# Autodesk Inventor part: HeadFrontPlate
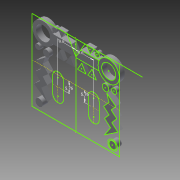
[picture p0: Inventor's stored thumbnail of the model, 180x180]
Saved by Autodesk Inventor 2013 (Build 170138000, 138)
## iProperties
Created: 2013-04
Part Number: HeadFrontPlate
Material: Generic
Document SubType Name: Modeling
Designer: frankenteddy
Density: 1 g/cm^3
Author: frankenteddy
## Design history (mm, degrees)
node "Blocks"
  sketch "Block3"
    geometry: L1 (42.096, -1.116)-(42.096, 7.884); L2 (48.096, 7.884)-(48.096, -1.116); L3 (62.096, -1.116)-(62.096, 7.884); L4 (68.096, 7.884)-(68.096, -1.116); L5 (78.596, -14.116)-(31.596, -14.116); L6 (78.596, 32.884)-(78.596, -14.116); L7 (31.596, 32.884)-(78.596, 32.884); L8 (31.596, -14.116)-(31.596, 32.884); L9 (55.096, -14.116)-(55.096, 32.884); L10 (78.596, 9.384)-(31.596, 9.384); A1 r 3 centre (45.096, 7.884) between (48.096, 7.884) and (42.096, 7.884); A2 r 3 centre (45.096, -1.116) between (42.096, -1.116) and (48.096, -1.116); A3 r 3 centre (65.096, -1.116) between (62.096, -1.116) and (68.096, -1.116); A4 r 3 centre (65.096, 7.884) between (68.096, 7.884) and (62.096, 7.884); 2 further points
    constraints: 20 end point, 8 point on circle, 4 centre point, 4 midpoint
sketch "Sketch2"
  geometry: L1 (-23.52, -21.6)-(23.52, -21.6); L2 (23.52, -21.6)-(23.52, 21.6); L3 (23.52, 21.6)-(-35.803, 21.6); L4 (-23.52, 21.6)-(-23.52, -21.6); L5 (0, 21.6)-(0, 13.22); L6 (23.52, 0)-(-23.52, 0); L7 (-12.48, -10.08)-(-12.48, -1.44); L8 (-6.72, -1.44)-(-6.72, -10.08); L9 (6.72, -10.08)-(6.72, -1.44); L10 (12.48, -1.44)-(12.48, -10.08); L11 (0, -22.56)-(0, 22.56); L12 (22.56, 0)-(-22.56, 0); L13 (-12.408, 17.606)-(-2.532, 17.606); L14 (0, 17.606)-(0, 12.839); L15 (-8.641, 11.767)-(-6.385, 7.86); L16 (-6.385, 7.86)-(-10.897, 7.86); L17 (-10.897, 7.86)-(-8.641, 11.767); L18 (-7.651, 18.184)-(-9.608, 21.574); L19 (-9.608, 21.574)-(-5.694, 21.574); L20 (-5.694, 21.574)-(-7.651, 18.184); L21 (0, 13.22)-(-2.532, 17.606); L22 (-4.826, 21.58)-(4.826, 21.58); L23 (4.977, 21.841)-(0, 13.22); L24 (-3.117, 11.767)-(-0.861, 7.86); L25 (-0.861, 7.86)-(-5.373, 7.86); L26 (-5.373, 7.86)-(-3.117, 11.767); L27 (-21.43, 0.817)-(-18.923, -2.057); L28 (-18.923, -2.057)-(-21.937, -4.687); L29 (-21.937, -4.687)-(-19.249, -7.768); L30 (-19.249, -7.768)-(-22.488, -10.594); L31 (-18.613, -10.524)-(-15.374, -7.698); L32 (-15.374, -7.698)-(-17.803, -4.914); L33 (-17.803, -4.914)-(-14.89, -2.373); L34 (-14.89, -2.373)-(-17.803, 0.967); L35 (-9.6, 1.44)-(-9.6, -12.96); L36 (9.6, 1.44)-(9.6, -12.96); L37 (6.72, -5.76)-(12.48, -5.76); L38 (-6.72, -5.76)-(-12.48, -5.76); L39 (-17.803, 0.967)-(-16.537, 4.5); L40 (-18.613, -10.524)-(-15.374, -15.435); L41 (-21.43, 0.817)-(-16.537, 4.5); L42 (-15.374, -15.435)-(-22.488, -10.594); L43 (0, 21.6)-(0, 13.22); L44 (0, 12.839)-(-12.441, 12.839); L45 (-2.532, 17.606)-(-4.977, 21.841); L46 (0, 13.22)-(0, -21.6); L47 (0, 13.22)-(0, -21.6); C1 r 3.788 at (-17.606, 15.258); C2 r 1.197 at (-11.393, 19.879); C3 r 1.766 at (-15.87, 6.755); C4 r 1.357 at (-20.543, 7.5); C5 r 2.564 at (-19.719, -18.011); C6 r 1.919 at (-19.719, -18.011); A1 r 2.88 centre (-9.6, -1.44) between (-6.72, -1.44) and (-12.48, -1.44); A2 r 2.88 centre (-9.6, -10.08) between (-12.48, -10.08) and (-6.72, -10.08); A3 r 2.88 centre (9.6, -10.08) between (6.72, -10.08) and (12.48, -10.08); A4 r 2.88 centre (9.6, -1.44) between (12.48, -1.44) and (6.72, -1.44); A5 r 5.703 centre (-17.606, 15.258) between (-12.441, 12.839) and (-12.408, 17.606); 6 further points
  constraints: 94 end point, 14 point on circle, 11 centre point, 7 midpoint, 7 point on line, 5 parallel, 3 collinear, 3 perpendicular, 1 horizontal, 22 other
  dimensions: "d4" = 9.6 distance between parallel lines of L5 L35; "d6" = 9.6 distance between parallel lines of L5 L36; "d9" = 5.76 distance between parallel lines of L12 L38; "d10" = 5.76 distance between parallel lines of L12 L37
extrude "Extrusion7" new body sketch "Sketch2" distance "d21" = 3; taper "d22" = 0 deg
extrude "Extrusion8" join sketch "Sketch2" distance "d23" = 2; taper "d24" = 0 deg
mirror "Mirror2"
body "Solid2"
sketch "Block2"
  geometry: L1 (-16.531, 18.34)-(0, 18.34); L2 (0, 18.34)-(0, 13.374); L3 (0, 13.374)-(-16.531, 13.374); L4 (-16.531, 13.374)-(-16.531, 18.34); L5 (-9.001, 12.258)-(-6.651, 8.188); L6 (-6.651, 8.188)-(-11.351, 8.188); L7 (-11.351, 8.188)-(-9.001, 12.258); L8 (-7.97, 18.942)-(-10.008, 22.473); L9 (-10.008, 22.473)-(-5.931, 22.473); L10 (-5.931, 22.473)-(-7.97, 18.942); L11 (0, 14.315)-(-4.713, 22.479); L12 (-4.713, 22.479)-(4.713, 22.479); L13 (4.713, 22.479)-(0, 14.315); L14 (-3.247, 12.258)-(-0.897, 8.188); L15 (-0.897, 8.188)-(-5.596, 8.188); L16 (-5.596, 8.188)-(-3.247, 12.258); L17 (-18.371, 3.533)-(-21.398, 0.891); L18 (-21.398, 0.891)-(-18.786, -2.103); L19 (-18.786, -2.103)-(-21.926, -4.842); L20 (-21.926, -4.842)-(-19.126, -8.052); L21 (-19.126, -8.052)-(-22.5, -10.995); L22 (-22.5, -10.995)-(-19.126, -14.862); L23 (-19.126, -14.862)-(-20.813, -10.995); L24 (-20.813, -10.995)-(-17.44, -8.052); L25 (-17.44, -8.052)-(-19.97, -5.152); L26 (-19.97, -5.152)-(-16.935, -2.504); L27 (-16.935, -2.504)-(-19.97, 0.975); L28 (-19.97, 0.975)-(-18.371, 3.533); C1 r 3.587 at (-18.339, 15.894); C2 r 5.941 at (-18.339, 15.894); C3 r 1.247 at (-11.868, 20.707); C4 r 1.839 at (-16.531, 7.036); C5 r 1.413 at (-21.398, 7.812); C6 r 2.671 at (-19.97, -19.404); C7 r 1.818 at (-19.97, -19.404); 5 further points
  constraints: 56 end point, 10 parallel, 7 centre point, 2 coincident, 2 perpendicular, 1 horizontal, 1 point on line, 28 other
node "Block2:2"
